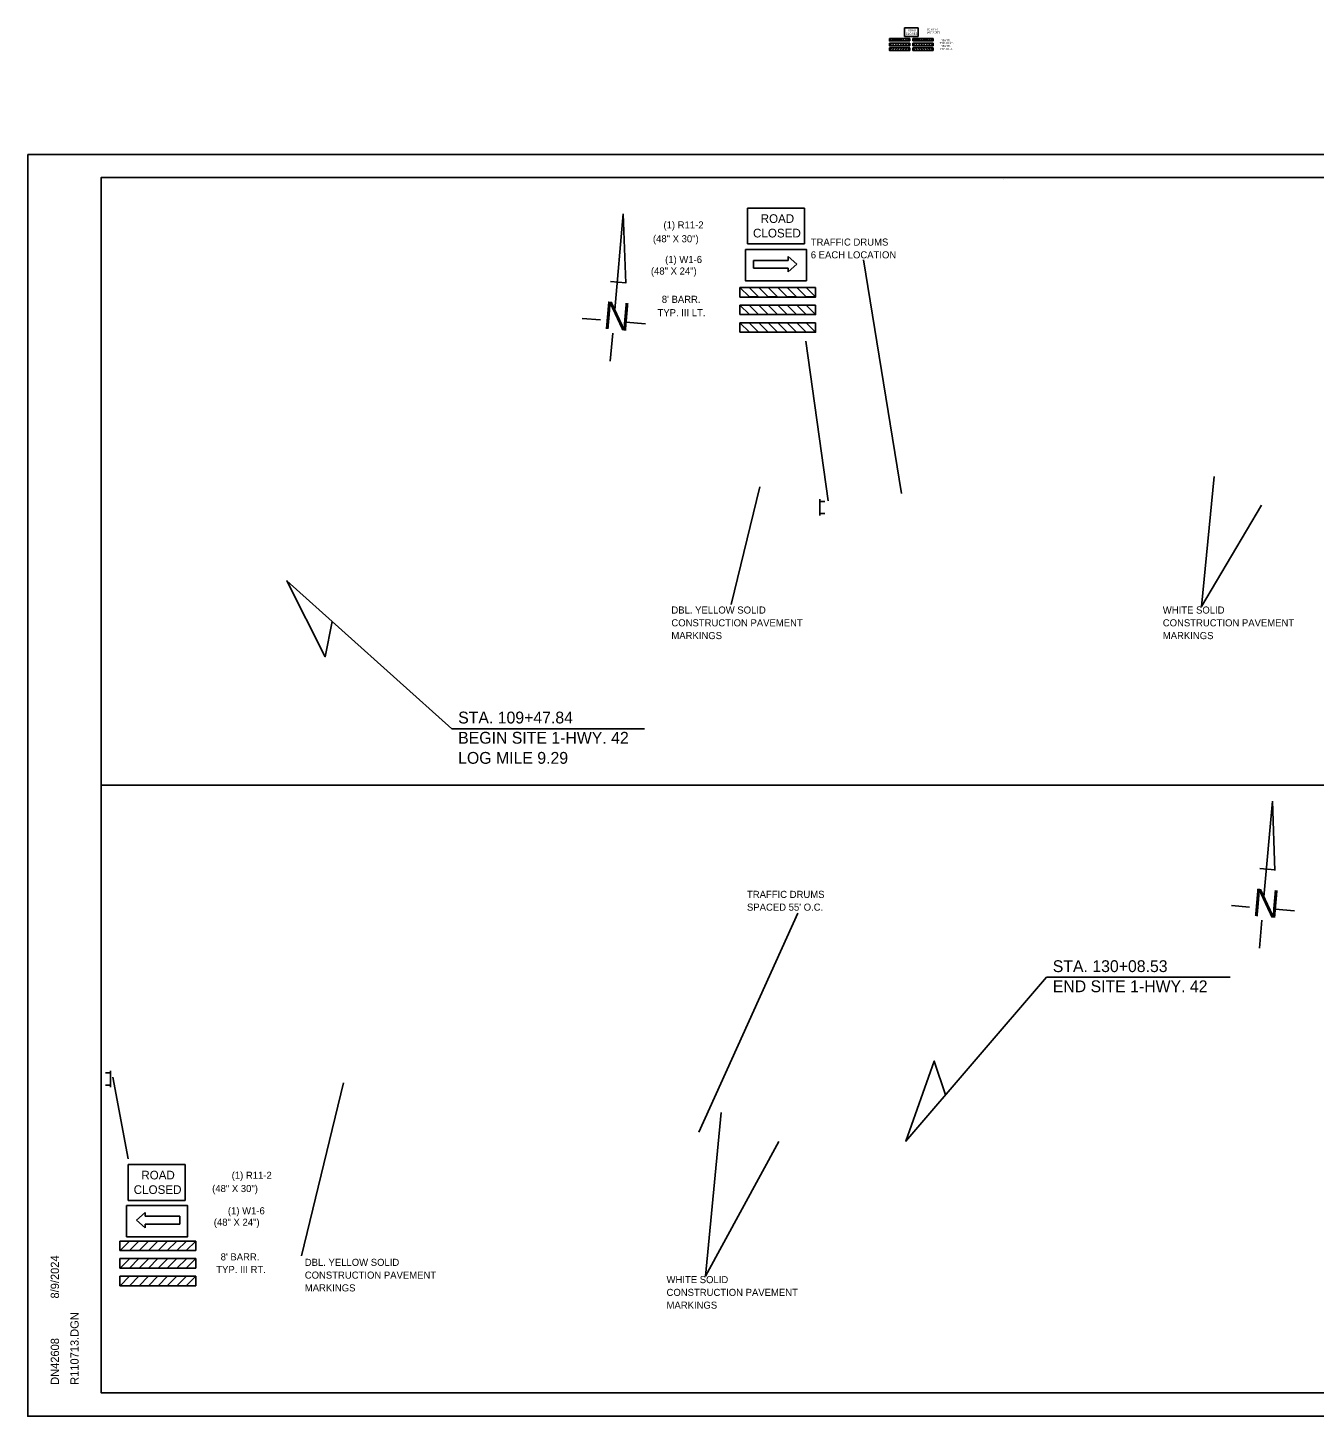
# Model space of a CAD drawing. Extents: x 1678017 to 1687792, y 404433 to 413488.
# Drawn here: x 1679754 to 1680841, y 407746 to 408920 of the extents above; entities that cross this region are included whole.
import ezdxf

# ---------------------------------------------------------------- set-up
doc = ezdxf.new("R2010")
doc.units = 0
for name, color, linetype in [('Default', 7, 'Continuous'), ('S_BUILDING', 7, 'Continuous'), ('S_GRAVEL_ROAD', 7, 'Continuous'), ('S_MSC_PT_SYM', 7, 'Continuous'), ('S_STREAM', 7, 'Continuous')]:
    doc.layers.add(name, color=color, linetype=linetype)

msp = doc.modelspace()

# ---------------------------------------------------------------- linework, layer by layer
at = {"layer": 'Default'}
for p, q in [((1680460.3, 408723.5), (1680492.4, 408525.9)), ((1680411.7, 408654.7), (1680430.4, 408519.6)), ((1680372.7, 408531.5), (1680348.6, 408432.1)), ((1680112.5, 408326.9), (1680275.3, 408326.9)), ((1680404.8, 408171.1), (1680321.3, 407985.8)), ((1680615, 408116.8), (1680770.1, 408116.8)), ((1679838.9, 407963.4), (1679825.9, 408032.4)), ((1680020.9, 408027.6), (1679985.3, 407881.4))]:
    msp.add_line(p, q, dxfattribs=at)
for points in [[(1680756.6, 408540.1), (1680746.1, 408430.3), (1680796.8, 408516)], [(1680112.5, 408326.9), (1679972.9, 408451.9), (1680005.5, 408387.8), (1680011.3, 408417.5)], [(1680615, 408116.8), (1680496.2, 407978.2), (1680520.1, 408046), (1680529.7, 408017.3)], [(1680340, 408002.4), (1680326.7, 407864.2), (1680388.7, 407978)]]:
    msp.add_lwpolyline(points, dxfattribs=at)
at = {"layer": 'S_BUILDING'}
for p, q in [((1679816.1, 408792.9), (1681397, 408792.9)), ((1679816.1, 407765.6), (1679816.1, 408792.9)), ((1680578.7, 408791.6), (1680578.7, 408791.6)), ((1680578.7, 408791.6), (1680578.7, 408791.6)), ((1679816.1, 408279.2), (1681397, 408279.2)), ((1679816.1, 407765.6), (1679816.1, 407765.6)), ((1681397, 407765.6), (1679816.1, 407765.6))]:
    msp.add_line(p, q, dxfattribs=at)
at = {"layer": 'S_GRAVEL_ROAD'}
for p, q in [((1680494.9, 408912.3), (1680494.9, 408919.6)), ((1680494.9, 408919.6), (1680506.6, 408919.6)), ((1680506.6, 408912.3), (1680506.6, 408919.6)), ((1680482.2, 408910.6), (1680499.4, 408910.6)), ((1680482.2, 408908.5), (1680482.2, 408910.6)), ((1680482.2, 408908.5), (1680499.4, 408908.5)), ((1680482.2, 408906.6), (1680499.4, 408906.6)), ((1680482.2, 408904.4), (1680482.2, 408906.6)), ((1680494.9, 408912.3), (1680506.6, 408912.3)), ((1680499.4, 408908.5), (1680499.4, 408910.6)), ((1680499.4, 408908.5), (1680499.4, 408908.5)), ((1680499.4, 408904.4), (1680499.4, 408906.6)), ((1680499.4, 408904.4), (1680499.4, 408906.6)), ((1680519.3, 408910.6), (1680502, 408910.6)), ((1680502, 408908.5), (1680502, 408910.6)), ((1680502, 408908.5), (1680502, 408908.5)), ((1680519.3, 408908.5), (1680502, 408908.5)), ((1680519.3, 408906.6), (1680502, 408906.6)), ((1680502, 408904.4), (1680502, 408906.6)), ((1680502, 408904.4), (1680502, 408906.6)), ((1680519.3, 408908.5), (1680519.3, 408910.6)), ((1680519.3, 408904.4), (1680519.3, 408906.6)), ((1680482.2, 408904.4), (1680499.4, 408904.4)), ((1680482.2, 408902.6), (1680499.4, 408902.6)), ((1680482.2, 408900.4), (1680482.2, 408902.6)), ((1680482.2, 408900.4), (1680499.4, 408900.4)), ((1680499.4, 408900.4), (1680499.4, 408902.6)), ((1680519.3, 408904.4), (1680502, 408904.4)), ((1680519.3, 408902.6), (1680502, 408902.6)), ((1680502, 408900.4), (1680502, 408902.6)), ((1680519.3, 408900.4), (1680502, 408900.4)), ((1680519.3, 408900.4), (1680519.3, 408902.6)), ((1680362.2, 408736.9), (1680362.2, 408767.1)), ((1680362.2, 408767.1), (1680410.5, 408767.1)), ((1680410.5, 408736.9), (1680410.5, 408767.1)), ((1680362.2, 408736.9), (1680410.5, 408736.9)), ((1680367.3, 408722.9), (1680396.7, 408722.9)), ((1680367.3, 408716.4), (1680367.3, 408722.9)), ((1680396.7, 408722.9), (1680396.7, 408726.2)), ((1680403.9, 408719.6), (1680396.7, 408726.2)), ((1680396.7, 408713.1), (1680403.9, 408719.6)), ((1680367.3, 408716.4), (1680396.7, 408716.4)), ((1680396.7, 408716.4), (1680396.7, 408713.1)), ((1680419.9, 408700), (1680355.9, 408700)), ((1680355.9, 408691.9), (1680355.9, 408700)), ((1680419.9, 408691.9), (1680419.9, 408700)), ((1680355.9, 408692), (1680355.9, 408692)), ((1680419.9, 408691.9), (1680355.9, 408691.9)), ((1680419.9, 408685.1), (1680355.9, 408685.1)), ((1680355.9, 408677.1), (1680355.9, 408685.1)), ((1680355.9, 408677.1), (1680355.9, 408685.1)), ((1680419.9, 408677.1), (1680419.9, 408685.1)), ((1680419.9, 408677.1), (1680355.9, 408677.1)), ((1680419.9, 408670.2), (1680355.9, 408670.2)), ((1680355.9, 408662.2), (1680355.9, 408670.2)), ((1680419.9, 408662.2), (1680355.9, 408662.2)), ((1680419.9, 408662.2), (1680419.9, 408670.2)), ((1680423.5, 408507.1), (1680423.5, 408520.9)), ((1680423.5, 408519), (1680427.7, 408519)), ((1680423.5, 408508.8), (1680427.7, 408508.8)), ((1679824, 408037.7), (1679824.1, 408023.8)), ((1679824, 408035.9), (1679819.8, 408035.9)), ((1679824.1, 408025.7), (1679819.9, 408025.7)), ((1679838.8, 407928.2), (1679838.8, 407958.4)), ((1679838.8, 407958.4), (1679887.1, 407958.4)), ((1679887.1, 407928.2), (1679887.1, 407958.4)), ((1679838.8, 407928.2), (1679887.1, 407928.2)), ((1679846, 407911.5), (1679853.2, 407918)), ((1679853.2, 407904.9), (1679846, 407911.5)), ((1679853.2, 407914.7), (1679853.2, 407918)), ((1679882.6, 407914.7), (1679853.2, 407914.7)), ((1679882.6, 407908.2), (1679853.2, 407908.2)), ((1679853.2, 407908.2), (1679853.2, 407904.9)), ((1679882.6, 407908.2), (1679882.6, 407914.7)), ((1679832, 407893.8), (1679896, 407893.8)), ((1679832, 407885.7), (1679832, 407893.8)), ((1679832, 407885.7), (1679896, 407885.7)), ((1679896, 407885.7), (1679896, 407893.8)), ((1679896, 407885.7), (1679896, 407885.8)), ((1679832, 407878.9), (1679896, 407878.9)), ((1679832, 407870.8), (1679832, 407878.9)), ((1679896, 407870.8), (1679896, 407878.9)), ((1679896, 407870.8), (1679896, 407878.9)), ((1679832, 407870.8), (1679896, 407870.8)), ((1679832, 407864), (1679896, 407864)), ((1679832, 407856), (1679832, 407864)), ((1679896, 407856), (1679896, 407864)), ((1679832, 407856), (1679896, 407856))]:
    msp.add_line(p, q, dxfattribs=at)
for points in [[(1680486.5, 408910.6), (1680484.4, 408910.6), (1680482.2, 408908.5), (1680484.3, 408908.5)], [(1680486.5, 408906.6), (1680484.4, 408906.6), (1680482.2, 408904.4), (1680484.3, 408904.4)], [(1680490.8, 408910.6), (1680488.7, 408910.6), (1680486.5, 408908.5), (1680488.6, 408908.5)], [(1680490.8, 408906.6), (1680488.7, 408906.6), (1680486.5, 408904.4), (1680488.6, 408904.4)], [(1680495.1, 408910.6), (1680493, 408910.6), (1680490.8, 408908.5), (1680493, 408908.5)], [(1680495.1, 408906.6), (1680493, 408906.6), (1680490.8, 408904.4), (1680493, 408904.4)], [(1680499.4, 408910.6), (1680497.3, 408910.6), (1680495.2, 408908.5), (1680497.3, 408908.5)], [(1680499.4, 408906.6), (1680497.3, 408906.6), (1680495.2, 408904.4), (1680497.3, 408904.4)], [(1680502, 408910.6), (1680504.1, 408910.6), (1680506.3, 408908.5), (1680504.2, 408908.5)], [(1680502, 408906.6), (1680504.1, 408906.6), (1680506.3, 408904.4), (1680504.2, 408904.4)], [(1680506.3, 408910.6), (1680508.4, 408910.6), (1680510.6, 408908.5), (1680508.5, 408908.5)], [(1680506.3, 408906.6), (1680508.4, 408906.6), (1680510.6, 408904.4), (1680508.5, 408904.4)], [(1680510.6, 408910.6), (1680512.8, 408910.6), (1680514.9, 408908.5), (1680512.8, 408908.5)], [(1680510.6, 408906.6), (1680512.8, 408906.6), (1680514.9, 408904.4), (1680512.8, 408904.4)], [(1680515, 408910.6), (1680517.1, 408910.6), (1680519.2, 408908.5), (1680517.1, 408908.5)], [(1680515, 408906.6), (1680517.1, 408906.6), (1680519.2, 408904.4), (1680517.1, 408904.4)], [(1680486.5, 408902.6), (1680484.4, 408902.6), (1680482.2, 408900.4), (1680484.3, 408900.4)], [(1680490.8, 408902.6), (1680488.7, 408902.6), (1680486.5, 408900.4), (1680488.6, 408900.4)], [(1680495.1, 408902.6), (1680493, 408902.6), (1680490.8, 408900.4), (1680493, 408900.4)], [(1680499.4, 408902.6), (1680497.3, 408902.6), (1680495.2, 408900.4), (1680497.3, 408900.4)], [(1680502, 408902.6), (1680504.1, 408902.6), (1680506.3, 408900.4), (1680504.2, 408900.4)], [(1680506.3, 408902.6), (1680508.4, 408902.6), (1680510.6, 408900.4), (1680508.5, 408900.4)], [(1680510.6, 408902.6), (1680512.8, 408902.6), (1680514.9, 408900.4), (1680512.8, 408900.4)], [(1680515, 408902.6), (1680517.1, 408902.6), (1680519.2, 408900.4), (1680517.1, 408900.4)], [(1680412.3, 408705.6), (1680360.7, 408705.6), (1680360.7, 408732), (1680412.3, 408732)], [(1680355.9, 408700), (1680363.7, 408700), (1680371.7, 408692), (1680363.9, 408692)], [(1680371.9, 408700), (1680379.8, 408700), (1680387.7, 408692), (1680379.9, 408692)], [(1680387.9, 408700), (1680395.8, 408700), (1680403.8, 408692), (1680395.9, 408692)], [(1680403.9, 408700), (1680411.8, 408700), (1680419.8, 408692), (1680411.9, 408692)], [(1680355.9, 408685.1), (1680363.7, 408685.1), (1680371.7, 408677.1), (1680363.9, 408677.1)], [(1680371.9, 408685.1), (1680379.8, 408685.1), (1680387.7, 408677.1), (1680379.9, 408677.1)], [(1680387.9, 408685.1), (1680395.8, 408685.1), (1680403.8, 408677.1), (1680395.9, 408677.1)], [(1680403.9, 408685.1), (1680411.8, 408685.1), (1680419.8, 408677.1), (1680411.9, 408677.1)], [(1680355.9, 408670.2), (1680363.7, 408670.2), (1680371.7, 408662.2), (1680363.9, 408662.2)], [(1680371.9, 408670.2), (1680379.8, 408670.2), (1680387.7, 408662.2), (1680379.9, 408662.2)], [(1680387.9, 408670.2), (1680395.8, 408670.2), (1680403.8, 408662.2), (1680395.9, 408662.2)], [(1680403.9, 408670.2), (1680411.8, 408670.2), (1680419.8, 408662.2), (1680411.9, 408662.2)], [(1679837.6, 407897.4), (1679889.1, 407897.4), (1679889.1, 407923.8), (1679837.6, 407923.8)], [(1679848, 407893.8), (1679840.1, 407893.7), (1679832.2, 407885.7), (1679840, 407885.7)], [(1679864, 407893.8), (1679856.2, 407893.7), (1679848.2, 407885.7), (1679856, 407885.7)], [(1679880, 407893.8), (1679872.2, 407893.7), (1679864.2, 407885.7), (1679872, 407885.7)], [(1679896, 407893.8), (1679888.2, 407893.7), (1679880.2, 407885.7), (1679888, 407885.7)], [(1679848, 407878.9), (1679840.1, 407878.8), (1679832.2, 407870.8), (1679840, 407870.8)], [(1679864, 407878.9), (1679856.2, 407878.8), (1679848.2, 407870.8), (1679856, 407870.8)], [(1679880, 407878.9), (1679872.2, 407878.8), (1679864.2, 407870.8), (1679872, 407870.8)], [(1679896, 407878.9), (1679888.2, 407878.8), (1679880.2, 407870.8), (1679888, 407870.8)], [(1679848, 407864), (1679840.1, 407864), (1679832.2, 407856), (1679840, 407856)], [(1679864, 407864), (1679856.2, 407864), (1679848.2, 407856), (1679856, 407856)], [(1679880, 407864), (1679872.2, 407864), (1679864.2, 407856), (1679872, 407856)], [(1679896, 407864), (1679888.2, 407864), (1679880.2, 407856), (1679888, 407856)]]:
    msp.add_lwpolyline(points, close=True, dxfattribs=at)
at = {"layer": 'S_MSC_PT_SYM'}
for p, q in [((1680250.2, 408681.1), (1680257.2, 408762.2)), ((1680257.2, 408762.2), (1680259.4, 408703.6)), ((1680246.6, 408705.1), (1680259.5, 408704)), ((1680222.7, 408673.9), (1680238, 408672.6)), ((1680246.3, 408637.7), (1680248.4, 408661.5)), ((1680259.5, 408670.7), (1680276, 408669.2)), ((1680798.8, 408184.8), (1680805.9, 408265.8)), ((1680805.9, 408265.8), (1680808, 408207.2)), ((1680795.2, 408208.8), (1680808.1, 408207.6)), ((1680771.3, 408177.5), (1680786.6, 408176.2)), ((1680808.2, 408174.3), (1680824.6, 408172.9)), ((1680795, 408141.3), (1680797, 408165.1))]:
    msp.add_line(p, q, dxfattribs=at)
at = {"layer": 'S_STREAM'}
for p, q in [((1679754.1, 408812.4), (1681420.8, 408812.4)), ((1679754.1, 407745.7), (1681420.8, 407745.7))]:
    msp.add_line(p, q, dxfattribs=at)
for points in [[(1679754.1, 408812.4), (1681420.8, 408812.4), (1681420.8, 407745.7), (1679754.1, 407745.7)], [(1681083.8, 408792.9), (1681083.8, 408743.5), (1681164.4, 408743.5), (1681164.4, 408728.9), (1681280.4, 408728.9), (1681280.4, 408607.2), (1681397, 408607.2), (1681397, 408279.2), (1679816.1, 408279.2), (1679816.1, 408792.9)], [(1680985.7, 408792.9), (1681083.8, 408792.9), (1681083.8, 408743.5), (1681164.4, 408743.5), (1681280.4, 408743.5), (1681280.4, 408621.8), (1681397, 408621.8), (1681397, 407765.6), (1679816.1, 407765.6), (1679816.1, 408792.9)], [(1681397, 408279.2), (1679816.1, 408279.2), (1679816.1, 407765.6), (1680929.6, 407765.6), (1680929.6, 407793.4), (1681085.2, 407793.4), (1681085.2, 407818.1), (1681397, 407818.1)]]:
    msp.add_lwpolyline(points, close=True, dxfattribs=at)

# ---------------------------------------------------------------- texts
at = {"layer": 'Default'}
for s, height, p in [('TRAFFIC DRUMS', 6, (1680415.8, 408735.4)), ('6 EACH LOCATION', 6, (1680415.8, 408724.6)), ('DBL. YELLOW SOLID', 6, (1680298, 408424.3)), ('WHITE SOLID', 6, (1680713.3, 408424.3)), ('CONSTRUCTION PAVEMENT', 6, (1680298, 408413.5)), ('CONSTRUCTION PAVEMENT', 6, (1680713.3, 408413.5)), ('MARKINGS', 6, (1680298, 408402.7)), ('MARKINGS', 6, (1680713.3, 408402.7)), ('STA. 109+47.84', 10, (1680117.8, 408331.4)), ('BEGIN SITE 1-HWY. 42', 10, (1680117.8, 408314.3)), ('LOG MILE 9.29', 10, (1680117.8, 408297.3)), ('TRAFFIC DRUMS', 6, (1680361.9, 408183.9)), ("SPACED 55' O.C.", 6, (1680361.9, 408173.1)), ('STA. 130+08.53', 10, (1680620.3, 408121.2)), ('END SITE 1-HWY. 42', 10, (1680620.3, 408104.2)), ('DBL. YELLOW SOLID', 6, (1679988.2, 407872.8)), ('CONSTRUCTION PAVEMENT', 6, (1679988.2, 407862)), ('WHITE SOLID', 6, (1680293.9, 407858.2)), ('MARKINGS', 6, (1679988.2, 407851.2)), ('CONSTRUCTION PAVEMENT', 6, (1680293.9, 407847.4)), ('MARKINGS', 6, (1680293.9, 407836.6))]:
    msp.add_text(s, height=height, dxfattribs=at).set_placement(p)
at = {"layer": 'S_BUILDING'}
for s, p in [('8/9/2024', (1679780.5, 407845.2)), ('R110713.DGN', (1679797.1, 407772.2)), ('DN42608', (1679780.5, 407772.2))]:
    msp.add_text(s, height=7, rotation=90, dxfattribs=at).set_placement(p)
at = {"layer": 'S_GRAVEL_ROAD'}
for s, height, p in [('ROAD', 1.78, (1680497.7, 408916.6)), ('(1) R11-2', 1.62, (1680514.1, 408917.3)), ('CLOSED', 1.78, (1680496.1, 408913.6)), ('(48" X 30")', 1.62, (1680514.1, 408914.9)), ('TYP. III RT.', 1.62, (1680524.8, 408905.8)), ("  ' BARR.", 1.62, (1680524.8, 408908.2)), ('TYP. III LT.', 1.62, (1680524.8, 408900.9)), ("  ' BARR.", 1.62, (1680524.8, 408903.4)), ('(1) R11-2', 6, (1680291.3, 408749.9)), ('ROAD', 7.31, (1680373.5, 408754.6)), ('(48" X 30")', 6, (1680282.4, 408738.2)), ('CLOSED', 7.35, (1680367, 408742.3)), ('(1) W1-6', 6, (1680292.7, 408720.7)), ('(48" X 24")', 6, (1680280.7, 408710.9)), ("8' BARR.", 6, (1680289.9, 408687)), ('TYP. III LT.', 6, (1680286.3, 408675.7)), ('ROAD', 7.31, (1679850.1, 407945.9)), ('(1) R11-2', 6, (1679926.4, 407946.4)), ('CLOSED', 7.35, (1679843.6, 407933.6)), ('(48" X 30")', 6, (1679909.9, 407935.2)), ('(1) W1-6', 6, (1679923.2, 407916.4)), ('(48" X 24")', 6, (1679911.3, 407906.7)), ("8' BARR.", 6, (1679917.1, 407877.4)), ('TYP. III RT.', 6, (1679913.4, 407866.7))]:
    msp.add_text(s, height=height, dxfattribs=at).set_placement(p)
at = {"layer": 'S_MSC_PT_SYM'}
for p in [(1680239.9, 408665.2), (1680788.5, 408168.8)]:
    msp.add_text('N', height=23.3, rotation=355, dxfattribs=at).set_placement(p)

doc.saveas('drawing.dxf')
